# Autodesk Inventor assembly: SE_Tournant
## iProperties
Shininess: 64.0
Length Units: 11269
Angle Units: 11279
Time Units: 11290
Mass Units: 11283
Length Display Precision: 3
Angle Display Precision: 2
Compacted: True
Created: 2005-01
Part Number: SE_Tournant
Document SubType Name: Assembly
Designer: MARTY
Density: 0.0
Volumn: 0.0
Area: 0.0
PropertySet Name: Model Information
Control State: 0
Master: False
Checked Out: False
Author: MARTY
